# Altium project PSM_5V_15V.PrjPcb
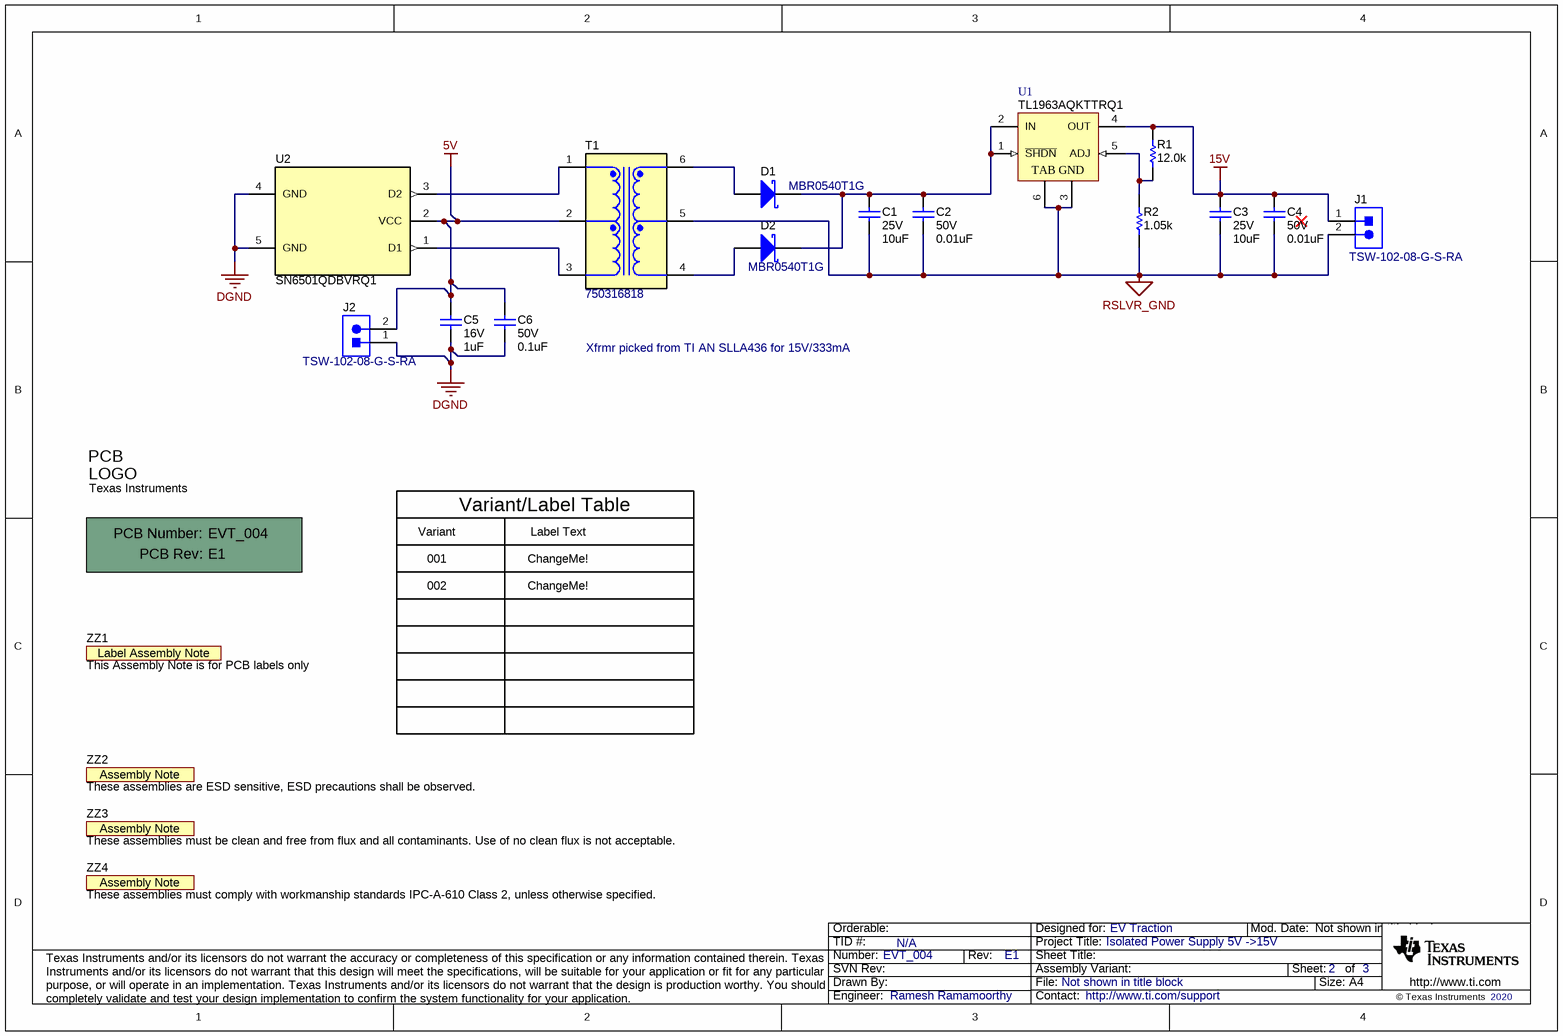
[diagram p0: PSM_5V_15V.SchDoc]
CopyrightYear: 2020; PCB_Layout: Ramesh Ramamoorthy; PCB_Rev: E1; PRJ_Customer: EV Traction; PRJ_Engineer: Ramesh Ramamoorthy; PRJ_Number: EVT_004; PRJ_Title: Isolated Power Supply 5V ->15V; SCH_Rev: E1; TechSupport: http://www.ti.com/support; TID: N/A
1 sheet, 21 parts. Net scope: global (net labels, ports and power ports of the same name join across sheets).
Board file: PSM_5V_15V.PcbDoc

## Sheet PSM_5V_15V.SchDoc
size A4; Date: Not shown in title block; ApprovedBy: Not shown in title block; CheckedBy: Not shown in title block; Author: Not shown in title block; CompanyName: Not shown in title block; Engineer: Not shown in title block; Organization: Not shown in title block; Address1: Not shown in title block; Address2: Not shown in title block; Address3: Not shown in title block; Address4: Not shown in title block; DocumentNumber: 2; Revision: Use project parameter SCH_Rev; SheetNumber: 2; SheetTotal: 3; PageSetup: Record=PageOptions¦CenterHorizontal=True¦CenterVertical=True¦PrintScale=1.00¦XCorrection=1.00¦YCorrection=1.00¦PrintKind=0¦BorderSize=5000000¦LeftOffset=0¦BottomOffset=0¦Orientation=2¦PaperLength=1000¦PaperWidth=1000¦Scale=100¦PaperSource=15¦PrintQuality=600¦MediaType=1¦DitherType=10¦PaperKind=Letter¦PrintScaleMode=1

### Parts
!PCB1  Printed Circuit Board  (value not drawn)  (mechanical)
C1  VDC_V: 25V  ValueDisplayed: 10uF  [0603]  (hidden comment: C1608X5R1E106M080AC)
C2  VDC_V: 50V  ValueDisplayed: 0.01uF  [0603]  (hidden comment: GCM188R71H103KA37D)
C3  VDC_V: 25V  ValueDisplayed: 10uF  [0603]  (hidden comment: C1608X5R1E106M080AC)
C4  VDC_V: 50V  ValueDisplayed: 0.01uF  [0603]  (hidden comment: GCM188R71H103KA37D)
C5  VDC_V: 16V  ValueDisplayed: 1uF  [0603]  (hidden comment: GCM188R71C105KA64D)
C6  VDC_V: 50V  ValueDisplayed: 0.1uF  [0603]  (hidden comment: CGA3E2X7R1H104K080AA)
D1  MBR0540T1G  [SOD-123]
D2  MBR0540T1G  [SOD-123]
J1  TSW-102-08-G-S-RA  [TSW-102-08-G-S-RA]
J2  TSW-102-08-G-S-RA  [TSW-102-08-G-S-RA]
Logo1  Texas Instruments  [TI_Symbol_Overlay_Small]  (no BOM)
R1  ValueDisplayed: 12.0k  [0805_HV]  (hidden comment: RG2012P-123-B-T5)
R2  ValueDisplayed: 1.05k  [0805_HV]  (hidden comment: RG2012P-1051-B-T5)
T1  750316818  [Wurth_750316029]
U1  TL1963AQKTTRQ1  [KTT0005A_N]
U2  SN6501QDBVRQ1  [DBV0005A_L]
ZZ1  This Assembly Note is for PCB labels only  [AssemblyNoteLabel]  (no BOM)
ZZ2  These assemblies are ESD sensitive, ESD precautions shall be observed.  [AssemblyNote]  (no BOM)
ZZ3  These assemblies must be clean and free from flux and all contaminants. Use of no clean flux is not acceptable.  [AssemblyNote]  (no BOM)
ZZ4  These assemblies must comply with workmanship standards IPC-A-610 Class 2, unless otherwise specified.  [AssemblyNote]  (no BOM)

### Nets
5V: C5.1 C6.1 J2.2 T1.2 U2.2(VCC)
15V: C3.1 C4.1 J1.1 R1.2 U1.4(OUT)
DGND: C5.2 C6.2 J2.1 U2.4(GND) U2.5(GND)
RSLVR_GND: C1.1 C2.2 C3.2 C4.2 J1.2 R2.1 T1.5 U1.3(GND) U1.6(TAB)
NetC1_2: C1.2 C2.1 D1.1(K) D2.1(K) U1.1(~{SHDN}) U1.2(IN)
NetD1_2: D1.2(A) T1.6
NetD2_2: D2.2(A) T1.4
NetR1_1: R1.1 R2.2 U1.5(ADJ)
NetT1_1: T1.1 U2.3(D2)
NetT1_3: T1.3 U2.1(D1)

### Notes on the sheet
- Xfrmr picked from TI AN SLLA436 for 15V/333mA
- Variant/Label Table
- Variant
- 001
- 002
- Label Text
- ChangeMe!

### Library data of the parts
!PCB1 = CMP-0003618-2: Manufacturer: Any; PartNumber: EVT_004
C1 C3 = CMP-0007007-5: CAP, CERM, 10 uF, 25 V, +/- 20%, X5R, 0603; Manufacturer: TDK; TaMin_C: -55°C; ESR_ohm: 4.639m; Polarized: N; SizeAreaWB_mm2: 4.68; Value1: 0.004639 ohm; U/M: EA; Value: 10uF; TaMax_C: 85°C; SizeZ_mm: 1; SizeX_mm: 1.6; SizeY_mm: 0.8; SizeArea_mm2: 1.28; Cap_F: 10µF; IRMS_A: 2.41407A; AEC Category: Q200
C2 C4 = CMP-0007143-4: CAP, CERM, 0.01 uF, 50 V, +/- 10%, X7R, AEC-Q200 Grade 1, 0603; Manufacturer: MuRata; TaMin_C: -55°C; Polarized: N; SizeAreaWB_mm2: 4.68; Value1: Unknown; U/M: EA; Value: 0.01uF; TaMax_C: 125°C; SizeZ_mm: 1; SizeX_mm: 1.6; SizeY_mm: 0.8; SizeArea_mm2: 1.28; AEC Qualified: Y; Cap_F: 10nF; AEC Category: Q200
C5 = CMP-0007136-5: CAP, CERM, 1 uF, 16 V, +/- 10%, X7R, AEC-Q200 Grade 1, 0603; Manufacturer: MuRata; TaMin_C: -55°C; Polarized: N; SizeAreaWB_mm2: 4.68; Value1: Unknown; U/M: EA; Value: 1uF; TaMax_C: 125°C; SizeZ_mm: 1; SizeX_mm: 1.6; SizeY_mm: 0.8; SizeArea_mm2: 1.28; AEC Qualified: Y; Cap_F: 1µF; AEC Category: Q200
C6 = CMP-0007078-4: CAP, CERM, 0.1 uF, 50 V, +/- 10%, X7R, AEC-Q200 Grade 1, 0603; Manufacturer: TDK; TaMin_C: -55°C; ESR_ohm: 0.0296; Polarized: N; SizeAreaWB_mm2: 4.68; Value1: 0.0296 ohm; U/M: EA; Value: 0.1uF; TaMax_C: 125°C; SizeZ_mm: 1; SizeX_mm: 1.6; SizeY_mm: 0.8; SizeArea_mm2: 1.28; AEC Qualified: Y; Cap_F: 100nF; IRMS_A: 9.7199dA; AEC Category: Q200
D1 D2 = CMP-0028526-2: Diode, Schottky, 40 V, 0.5 A, SOD-123; Manufacturer: ON Semiconductor; Green_REACh: Passed; SizeY_mm: 1.7; Io_A: 500mA; SizeArea_mm2: 6.545; RJC_CperW: 118; Green_Lifecycle: Active; Vr_V: 40V; Vf_V: 510mV; TJmax_C: 150°C; AEC Category: Q101; SizeAreaWB_mm2: 13.095; Value1: 0.5A; SizeZ_mm: 1.35; SizeX_mm: 3.85; Value2: 0.51V; Value: 40V
J1 J2 = CMP-0055976-1: Header, 100mil, 2x1, Gold, R/A, TH; Manufacturer: Samtec; Cert_VDE: N; CNHeader: FALSE; Current_A: 6.3A; Green_Lifecycle: Active; Gender: Male; Cert_CSA: Y; Green_REACh: Passed; Voltage_V: 550V; Row_Count: 1; Pitch_mm: 2.54
Logo1 = CMP-0074838-1: Texas Instrument Corporate Signature; SymbolCreator: a0412235; Lib Reference: TI_Logo; Library Reference: Logo
R1 = CMP-0018871-2: RES, 12.0 k, 0.1%, 0.125 W, 0805; Manufacturer: Susumu Co Ltd; Power_W: 125mW; TempCo: 25 ppm/C; Value_Code: 12k0; U/M: EA; Value: 12.0k; EIA_Code: E192; Res_ohm: 12k; SizeX_mm: 2; SizeY_mm: 1.25; SizeZ_mm: 1.45; Value2: 0.125W; SizeArea_mm2: 2.5; VDC_V: 100V; AEC Category: Q200
R2 = CMP-0018858-1: RES, 1.05 k, 0.1%, 0.125 W, 0805; Manufacturer: Susumu Co Ltd; Power_W: 125mW; TempCo: 25 ppm/C; Value_Code: 1k05; U/M: EA; Value: 1.05k; EIA_Code: E192; SizeX_mm: 2; SizeY_mm: 1.25; SizeZ_mm: 1.45; Value2: 0.125W; SizeArea_mm2: 2.5; VDC_V: 100V; AEC Category: Q200
T1 = CMP-0067601-1: Transformer, 94 uH, SMT; Manufacturer: Wurth Elektronik; SizeAreaWB_mm2: 150.38; DCR_ohm: 0.1; Value: 94uH; Lp: 94.0; SizeZ_mm: 4.1; SizeX_mm: 12.6; SizeY_mm: 8.3; Ns1toNp: 3.5; SizeArea_mm2: 104.58; Ind_H: 94µH; Rsec1_ohm: 0.6
U1 = CMP-0036893-1: Single Output Fast Transient Response LDO, 1.5 A, Adjustable 1.21 to 20 V Output, 2.1 to 20 V Input, 5-pin DDPAK (KTT), -40 to 125 degC, Green (RoHS & no Sb/Br); Manufacturer: Texas Instruments; Vin(Min)(V): 2.1; SubFamily: Single Channel LDO; Vdo(Typ)(mV): 340; Iq(Typ)(mA): 1; Vout Adj(Min)(V): 1.21; Vin(Max)(V): 20; Iout(Max)(A): 1.5
U2 = CMP-0076093-1: Automotive Low-Noise 350 mA, 410 kHz Transformer Driver, DBV0005A (SOT-23-5); Manufacturer: Texas Instruments; SizeAreaWB_mm2: 14.82; SizeArea_mm2: 8.12; SizeZ_mm: 1.45; SizeY_mm: 2.9; U/M: EA; CompType: IC; SizeX_mm: 2.8
ZZ1 = CMP-0003616-3
ZZ2 = CMP-0077236-1
ZZ3 = CMP-0077237-1
ZZ4 = CMP-0077238-1

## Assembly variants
001: all parts fitted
